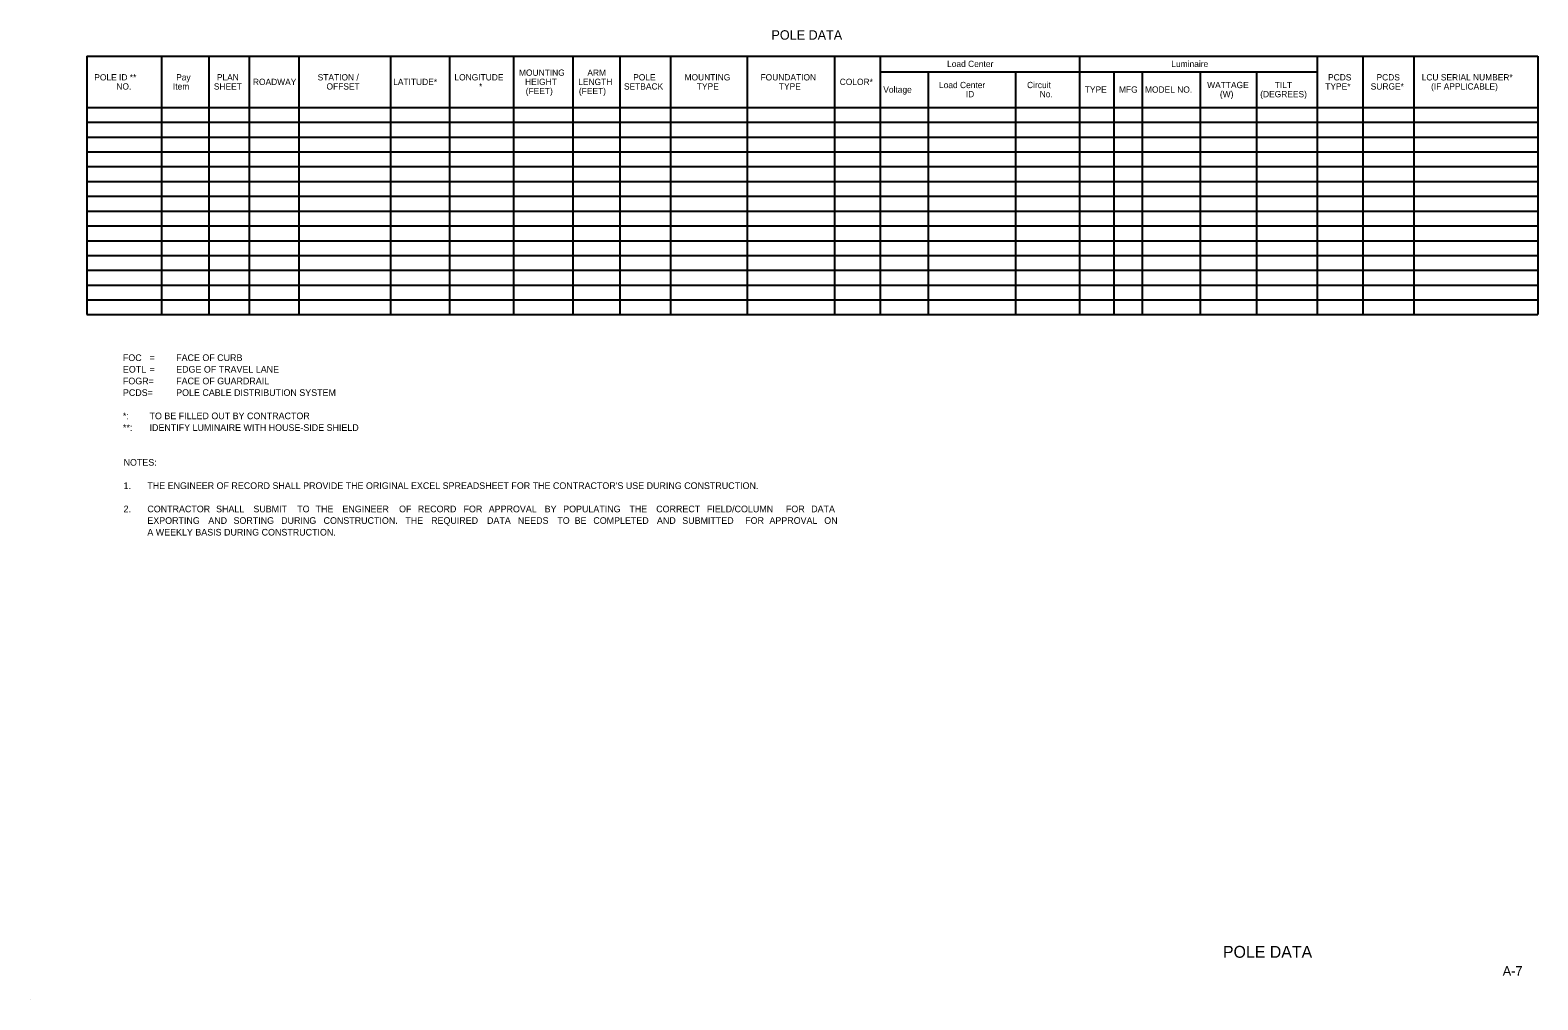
# Model space of a CAD drawing. Extents: x -830028.7 to -830012.8, y 1290283.4 to 1290293.6.
import ezdxf

# ---------------------------------------------------------------- set-up
doc = ezdxf.new("R2010")
doc.units = 0
for name, color, linetype in [('AdhocPoint_dp', 7, 'Continuous'), ('SumBoxBorder_dp', 7, 'Continuous'), ('SumBoxLines_dp', 7, 'Continuous'), ('SumBoxLinesMin_dp', 7, 'Continuous'), ('TextLabel', 7, 'Continuous'), ('TextMisc', 7, 'Continuous'), ('TextNotes', 7, 'Continuous'), ('TextShtNo', 7, 'Continuous')]:
    doc.layers.add(name, color=color, linetype=linetype)

msp = doc.modelspace()

# ---------------------------------------------------------------- linework, layer by layer
at = {"layer": 'AdhocPoint_dp'}
msp.add_line((-830028.694, 1290283.415), (-830028.694, 1290283.415), dxfattribs=at)
at = {"layer": 'SumBoxBorder_dp'}
for p, q in [((-830028.097, 1290293.343), (-830012.839, 1290293.343)), ((-830028.097, 1290293.343), (-830012.839, 1290293.343)), ((-830028.097, 1290293.343), (-830028.097, 1290290.624)), ((-830027.311, 1290293.343), (-830027.311, 1290292.803)), ((-830027.311, 1290293.343), (-830027.311, 1290292.803)), ((-830026.816, 1290293.343), (-830026.816, 1290292.803)), ((-830026.816, 1290293.343), (-830026.816, 1290292.803)), ((-830026.391, 1290293.343), (-830026.391, 1290292.803)), ((-830026.391, 1290293.343), (-830026.391, 1290292.803)), ((-830025.868, 1290293.343), (-830025.868, 1290292.803)), ((-830025.868, 1290293.343), (-830025.868, 1290292.803)), ((-830024.905, 1290293.343), (-830024.905, 1290292.803)), ((-830024.905, 1290293.343), (-830024.905, 1290292.803)), ((-830024.282, 1290293.343), (-830024.282, 1290292.803)), ((-830024.282, 1290293.343), (-830024.282, 1290292.803)), ((-830023.61, 1290293.343), (-830023.61, 1290292.803)), ((-830023.61, 1290293.343), (-830023.61, 1290292.803)), ((-830022.987, 1290293.343), (-830022.987, 1290292.803)), ((-830022.987, 1290293.343), (-830022.987, 1290292.803)), ((-830022.492, 1290293.343), (-830022.492, 1290292.803)), ((-830022.492, 1290293.343), (-830022.492, 1290292.803)), ((-830021.961, 1290293.343), (-830021.961, 1290292.803)), ((-830021.961, 1290293.343), (-830021.961, 1290292.803)), ((-830021.154, 1290293.343), (-830021.154, 1290292.803)), ((-830021.154, 1290293.343), (-830021.154, 1290292.803)), ((-830020.234, 1290293.343), (-830020.234, 1290292.803)), ((-830020.234, 1290293.343), (-830020.234, 1290292.803)), ((-830019.753, 1290293.343), (-830019.753, 1290292.803)), ((-830019.753, 1290293.343), (-830019.753, 1290292.803)), ((-830017.658, 1290293.343), (-830017.658, 1290292.803)), ((-830017.658, 1290293.343), (-830017.658, 1290292.803)), ((-830015.16, 1290293.343), (-830015.16, 1290292.803)), ((-830015.16, 1290293.343), (-830015.16, 1290292.803)), ((-830014.679, 1290293.343), (-830014.679, 1290292.803)), ((-830014.679, 1290293.343), (-830014.679, 1290292.803)), ((-830014.141, 1290293.343), (-830014.141, 1290292.803)), ((-830014.141, 1290293.343), (-830014.141, 1290292.803)), ((-830012.839, 1290293.343), (-830012.839, 1290290.624)), ((-830019.753, 1290293.18), (-830015.16, 1290293.18)), ((-830019.753, 1290293.18), (-830015.16, 1290293.18)), ((-830019.25, 1290293.18), (-830019.25, 1290292.803)), ((-830019.25, 1290293.18), (-830019.25, 1290292.803)), ((-830018.33, 1290293.18), (-830018.33, 1290292.803)), ((-830018.33, 1290293.18), (-830018.33, 1290292.803)), ((-830017.297, 1290293.18), (-830017.297, 1290292.803)), ((-830017.297, 1290293.18), (-830017.297, 1290292.803)), ((-830017, 1290293.18), (-830017, 1290292.803)), ((-830017, 1290293.18), (-830017, 1290292.803)), ((-830016.391, 1290293.18), (-830016.391, 1290292.803)), ((-830016.391, 1290293.18), (-830016.391, 1290292.803)), ((-830015.797, 1290293.18), (-830015.797, 1290292.803)), ((-830015.797, 1290293.18), (-830015.797, 1290292.803)), ((-830028.097, 1290292.803), (-830012.839, 1290292.803)), ((-830028.097, 1290292.803), (-830012.839, 1290292.803)), ((-830028.097, 1290290.624), (-830012.839, 1290290.624))]:
    msp.add_line(p, q, dxfattribs=at)
at = {"layer": 'SumBoxLines_dp'}
for p, q in [((-830027.311, 1290292.803), (-830027.311, 1290290.624)), ((-830027.311, 1290292.803), (-830027.311, 1290290.624)), ((-830026.816, 1290292.803), (-830026.816, 1290290.624)), ((-830026.816, 1290292.803), (-830026.816, 1290290.624)), ((-830026.391, 1290292.803), (-830026.391, 1290290.624)), ((-830026.391, 1290292.803), (-830026.391, 1290290.624)), ((-830025.868, 1290292.803), (-830025.868, 1290290.624)), ((-830025.868, 1290292.803), (-830025.868, 1290290.624)), ((-830024.905, 1290292.803), (-830024.905, 1290290.624)), ((-830024.905, 1290292.803), (-830024.905, 1290290.624)), ((-830024.282, 1290292.803), (-830024.282, 1290290.624)), ((-830024.282, 1290292.803), (-830024.282, 1290290.624)), ((-830023.61, 1290292.803), (-830023.61, 1290290.624)), ((-830023.61, 1290292.803), (-830023.61, 1290290.624)), ((-830022.987, 1290292.803), (-830022.987, 1290290.624)), ((-830022.987, 1290292.803), (-830022.987, 1290290.624)), ((-830022.492, 1290292.803), (-830022.492, 1290290.624)), ((-830022.492, 1290292.803), (-830022.492, 1290290.624)), ((-830021.961, 1290292.803), (-830021.961, 1290290.624)), ((-830021.961, 1290292.803), (-830021.961, 1290290.624)), ((-830021.154, 1290292.803), (-830021.154, 1290290.624)), ((-830021.154, 1290292.803), (-830021.154, 1290290.624)), ((-830020.234, 1290292.803), (-830020.234, 1290290.624)), ((-830020.234, 1290292.803), (-830020.234, 1290290.624)), ((-830019.753, 1290292.803), (-830019.753, 1290290.624)), ((-830019.753, 1290292.803), (-830019.753, 1290290.624)), ((-830019.25, 1290292.803), (-830019.25, 1290290.624)), ((-830019.25, 1290292.803), (-830019.25, 1290290.624)), ((-830018.33, 1290292.803), (-830018.33, 1290290.624)), ((-830018.33, 1290292.803), (-830018.33, 1290290.624)), ((-830017.658, 1290292.803), (-830017.658, 1290290.624)), ((-830017.658, 1290292.803), (-830017.658, 1290290.624)), ((-830017.297, 1290292.803), (-830017.297, 1290290.624)), ((-830017.297, 1290292.803), (-830017.297, 1290290.624)), ((-830017, 1290292.803), (-830017, 1290290.624)), ((-830017, 1290292.803), (-830017, 1290290.624)), ((-830016.391, 1290292.803), (-830016.391, 1290290.624)), ((-830016.391, 1290292.803), (-830016.391, 1290290.624)), ((-830015.797, 1290292.803), (-830015.797, 1290290.624)), ((-830015.797, 1290292.803), (-830015.797, 1290290.624)), ((-830015.16, 1290292.803), (-830015.16, 1290290.624)), ((-830015.16, 1290292.803), (-830015.16, 1290290.624)), ((-830014.679, 1290292.803), (-830014.679, 1290290.624)), ((-830014.141, 1290292.803), (-830014.141, 1290290.624))]:
    msp.add_line(p, q, dxfattribs=at)
at = {"layer": 'SumBoxLinesMin_dp'}
for p, q in [((-830028.097, 1290292.648), (-830012.839, 1290292.648)), ((-830028.097, 1290292.648), (-830012.839, 1290292.648)), ((-830028.097, 1290292.492), (-830012.839, 1290292.492)), ((-830028.097, 1290292.492), (-830012.839, 1290292.492)), ((-830028.097, 1290292.336), (-830012.839, 1290292.336)), ((-830028.097, 1290292.336), (-830012.839, 1290292.336)), ((-830028.097, 1290292.181), (-830012.839, 1290292.181)), ((-830028.097, 1290292.181), (-830012.839, 1290292.181)), ((-830028.097, 1290292.025), (-830012.839, 1290292.025)), ((-830028.097, 1290292.025), (-830012.839, 1290292.025)), ((-830028.097, 1290291.869), (-830012.839, 1290291.869)), ((-830028.097, 1290291.869), (-830012.839, 1290291.869)), ((-830028.097, 1290291.714), (-830012.839, 1290291.714)), ((-830028.097, 1290291.714), (-830012.839, 1290291.714)), ((-830028.097, 1290291.558), (-830012.839, 1290291.558)), ((-830028.097, 1290291.558), (-830012.839, 1290291.558)), ((-830028.097, 1290291.402), (-830012.839, 1290291.402)), ((-830028.097, 1290291.402), (-830012.839, 1290291.402)), ((-830028.097, 1290291.247), (-830012.839, 1290291.247)), ((-830028.097, 1290291.247), (-830012.839, 1290291.247)), ((-830028.097, 1290291.091), (-830012.839, 1290291.091)), ((-830028.097, 1290291.091), (-830012.839, 1290291.091)), ((-830028.097, 1290290.935), (-830012.839, 1290290.935)), ((-830028.097, 1290290.935), (-830012.839, 1290290.935)), ((-830028.097, 1290290.779), (-830012.839, 1290290.779)), ((-830028.097, 1290290.779), (-830012.839, 1290290.779))]:
    msp.add_line(p, q, dxfattribs=at)

# ---------------------------------------------------------------- texts
at = {"layer": 'TextLabel'}
for s, height, p in [('POLE DATA', 0.0991, (-830020.898, 1290293.517)), ('Load Center', 0.06605, (-830019.051, 1290293.229)), ('Luminaire', 0.0661, (-830016.693, 1290293.229)), ('POLE ID **', 0.0661, (-830028.019, 1290293.088)), ('Pay', 0.0661, (-830027.158, 1290293.088)), ('PLAN', 0.0661, (-830026.73, 1290293.088)), ('ROADWAY', 0.0661, (-830026.351, 1290293.04)), ('STATION /', 0.0661, (-830025.67, 1290293.088)), ('LATITUDE*', 0.0661, (-830024.876, 1290293.04)), ('LONGITUDE', 0.0661, (-830024.232, 1290293.088)), ('MOUNTING', 0.0661, (-830023.553, 1290293.137)), ('HEIGHT', 0.0661, (-830023.489, 1290293.04)), ('LENGTH', 0.0661, (-830022.93, 1290293.04)), ('ARM', 0.0661, (-830022.834, 1290293.137)), ('POLE', 0.0661, (-830022.352, 1290293.088)), ('MOUNTING', 0.0661, (-830021.812, 1290293.088)), ('FOUNDATION', 0.0661, (-830021.013, 1290293.088)), ('COLOR*', 0.0661, (-830020.18, 1290293.04)), ('PCDS', 0.0661, (-830015.045, 1290293.088)), ('PCDS', 0.0661, (-830014.535, 1290293.088)), ('LCU SERIAL NUMBER*', 0.06605, (-830014.06, 1290293.088)), ('NO.', 0.0661, (-830027.787, 1290292.992)), ('Item', 0.0661, (-830027.192, 1290292.992)), ('SHEET', 0.0661, (-830026.762, 1290292.992)), ('OFFSET', 0.0661, (-830025.577, 1290292.992)), ('*', 0.0661, (-830023.973, 1290292.992)), ('(FEET)', 0.0661, (-830023.482, 1290292.944)), ('(FEET)', 0.0661, (-830022.923, 1290292.944)), ('SETBACK', 0.0661, (-830022.449, 1290292.992)), ('TYPE', 0.0661, (-830021.683, 1290292.992)), ('TYPE', 0.0661, (-830020.82, 1290292.992)), ('Voltage', 0.0661, (-830019.722, 1290292.959)), ('Load Center', 0.06605, (-830019.136, 1290293.007)), ('ID', 0.0661, (-830018.854, 1290292.911)), ('Circuit', 0.0661, (-830018.21, 1290293.007)), ('No.', 0.0661, (-830018.077, 1290292.911)), ('TYPE', 0.0661, (-830017.603, 1290292.959)), ('MFG', 0.0661, (-830017.243, 1290292.959)), ('MODEL NO.', 0.0661, (-830016.97, 1290292.959)), ('WATTAGE', 0.0661, (-830016.316, 1290293.007)), ('(W)', 0.0661, (-830016.182, 1290292.911)), ('(DEGREES)', 0.0661, (-830015.758, 1290292.911)), ('TILT', 0.0661, (-830015.605, 1290293.007)), ('TYPE*', 0.0661, (-830015.074, 1290292.992)), ('SURGE*', 0.0661, (-830014.596, 1290292.992)), ('(IF APPLICABLE)', 0.06605, (-830013.961, 1290292.992)), ('FOC', 0.07, (-830027.718, 1290290.136)), ('EOTL', 0.07, (-830027.718, 1290290.014)), ('=', 0.07, (-830027.438, 1290290.136)), ('FACE OF CURB', 0.07, (-830027.158, 1290290.136)), ('EDGE OF TRAVEL LANE', 0.07, (-830027.158, 1290290.014)), ('FOGR=', 0.07, (-830027.718, 1290289.891)), ('=', 0.07, (-830027.438, 1290290.014)), ('FACE OF GUARDRAIL', 0.07, (-830027.158, 1290289.891)), ('PCDS=', 0.07, (-830027.718, 1290289.769)), ('POLE CABLE DISTRIBUTION SYSTEM', 0.07, (-830027.158, 1290289.769)), ('*: ', 0.07, (-830027.718, 1290289.524)), ('**:', 0.07, (-830027.718, 1290289.401)), ('TO BE FILLED OUT BY CONTRACTOR', 0.07, (-830027.438, 1290289.524)), ('IDENTIFY LUMINAIRE WITH HOUSE-SIDE SHIELD', 0.07, (-830027.438, 1290289.401))]:
    msp.add_text(s, height=height, dxfattribs=at).set_placement(p)
at = {"layer": 'TextMisc'}
msp.add_text('       POLE DATA       ', height=0.125, dxfattribs=at).set_placement((-830016.475, 1290283.858))
at = {"layer": 'TextNotes'}
for s, p in [('NOTES:', (-830027.711, 1290289.035)), ('1.', (-830027.711, 1290288.79)), ("THE ENGINEER OF RECORD SHALL PROVIDE THE ORIGINAL EXCEL SPREADSHEET FOR THE CONTRACTOR'S USE DURING CONSTRUCTION.", (-830027.461, 1290288.79)), ('2.', (-830027.711, 1290288.545)), ('CONTRACTOR ', (-830027.461, 1290288.545)), ('EXPORTING ', (-830027.461, 1290288.423)), ('AND ', (-830026.82, 1290288.423)), ('SHALL ', (-830026.738, 1290288.545)), ('SORTING ', (-830026.555, 1290288.423)), ('SUBMIT ', (-830026.346, 1290288.545)), ('DURING ', (-830026.054, 1290288.423)), ('TO ', (-830025.885, 1290288.545)), ('THE ', (-830025.692, 1290288.545)), ('CONSTRUCTION. ', (-830025.608, 1290288.423)), ('ENGINEER ', (-830025.41, 1290288.545)), ('OF ', (-830024.814, 1290288.545)), ('THE ', (-830024.748, 1290288.423)), ('RECORD ', (-830024.617, 1290288.545)), ('REQUIRED ', (-830024.477, 1290288.423)), ('FOR ', (-830024.136, 1290288.545)), ('DATA ', (-830023.889, 1290288.423)), ('APPROVAL ', (-830023.871, 1290288.545)), ('NEEDS ', (-830023.565, 1290288.423)), ('BY ', (-830023.283, 1290288.545)), ('TO ', (-830023.15, 1290288.423)), ('POPULATING ', (-830023.088, 1290288.545)), ('BE ', (-830022.968, 1290288.423)), ('COMPLETED ', (-830022.771, 1290288.423)), ('THE ', (-830022.392, 1290288.545)), ('CORRECT ', (-830022.11, 1290288.545)), ('AND ', (-830022.102, 1290288.423)), ('SUBMITTED ', (-830021.836, 1290288.423)), ('FIELD/COLUMN ', (-830021.577, 1290288.545)), ('FOR ', (-830021.174, 1290288.423)), ('APPROVAL ', (-830020.919, 1290288.423)), ('FOR ', (-830020.746, 1290288.545)), ('DATA ', (-830020.48, 1290288.545)), ('ON ', (-830020.343, 1290288.423)), ('A WEEKLY BASIS DURING CONSTRUCTION. ', (-830027.461, 1290288.3))]:
    msp.add_text(s, height=0.07, dxfattribs=at).set_placement(p)
at = {"layer": 'TextShtNo'}
msp.add_text('A-7', height=0.1, dxfattribs=at).set_placement((-830013.208, 1290283.67))

doc.saveas('drawing.dxf')
